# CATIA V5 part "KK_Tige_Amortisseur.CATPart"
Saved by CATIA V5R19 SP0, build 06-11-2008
Part number: Tige d'amortisseur
Bounding box of the stored display mesh (mm): x -480 to 480, y 640 to 1407.954, z -3231.87 to -864
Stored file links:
  G:\Khaled_CFAO_2011\ST2M\ST2M_GR2\aboulegue\Khaled\CAD_thinkMOTION\KK_Tige_Amortisseur.CATPart
  G:\Khaled_CFAO_2011\ST2M\ST2M_GR2\aboulegue\Khaled\CAD_thinkMOTION\KK_Train_Atterrissage.CATProduct
  G:\Khaled_CFAO_2011\ST2M\ST2M_GR2\aboulegue\Khaled\CAD_thinkMOTION\KK_Squelette_TigeAmortisseur.CATPart
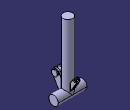
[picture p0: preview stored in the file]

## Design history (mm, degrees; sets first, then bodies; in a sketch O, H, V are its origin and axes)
Set1
  Plane1 "Plan de reference tige amortisseur": linked copy from another document
  Line1: linked copy from another document
  Point1: linked copy from another document
  Point2 "Point.17": linked copy from another document
  Plane2 "Plan de reference tige amortisseur2": linked copy from another document
  Line2: linked copy from another document
  Line3: linked copy from another document
  Point3: linked copy from another document
  Line4: linked copy from another document
  Point4: linked copy from another document
Body1 (main body)
  Sketch1 on Plane1, origin (0, 1056, 0), H (-1, 0, 0), V (0, 0, 1)
    point P1 (0, -864)
    line L1 (0, -864) -> (160, -864)
    line L2 (160, -864) -> (160, -3072)
    line L3 (160, -3072) -> (0, -3072)
    line L4 (0, -3072) -> (0, -864)
    point P4 (0, -3072)
    reference projected line E1 (0, -864) -> (0, -3072) from Line1
    reference projected point E2 (0, -3072) from Point1
    reference projected point E3 (0, -864) from Point2
    length L3 = 160
    horizontal: L1 H, L3 H
    vertical: L2 V, L4 V
    coincidence: E1 L4, E2 P4, P1 E3
  Shaft1: profile Sketch1, axis Line1, angle 360
  Sketch2 on Plane2, origin (0, 0, 0), H (0, 1, 0), V (0, 0, 1)
    circle A1 centre (1056, -3072) radius 160
    point P1 (1056, -3072)
    reference projected point E1 (1056, -3072) from Point1
    radius A1 = 160
    coincidence: E1 P1
  Pad1: profile Sketch2, direction (1, 0, 0), length 480, mirrored extent
  Plane3: type Normal, Curve Line3, RefPoint Point1
  Sketch3 on Plane3, origin (0, -982.6138, -1848.8317), H (1, 0, 0), V (0, -0.8575, 0.5145)
    line L1 (32, -2313.4118) -> (64, -2313.4118)
    line L2 (64, -2313.4118) -> (64, -2441.4118)
    line L3 (64, -2441.4118) -> (32, -2441.4118)
    line L4 (32, -2441.4118) -> (32, -2313.4118)
    point P5 (-64, -2313.4118)
    line L5 (-64, -2313.4118) -> (-32, -2313.4118)
    line L6 (-32, -2313.4118) -> (-32, -2441.4118)
    line L7 (-32, -2441.4118) -> (-64, -2441.4118)
    line L8 (-64, -2441.4118) -> (-64, -2313.4118)
    point P7 (-32, -2441.4118)
    reference projected line E1 (0, -1338.3529) -> (0, -2377.4118) from Line1
    reference projected line E2 (0, -1338.3529) -> (0, -2377.4118) from Line1
    reference projected line E3 (-200, -2377.4118) -> (200, -2377.4118) from Line2
    reference projected line E4 (-200, -2377.4118) -> (200, -2377.4118) from Line2
    length L3 = 32
    length L7 = 32
    distance E1 L4 = 32
    distance L6 E2 = 32
    distance E3 L7 = 64
    distance E4 L5 = 64
    horizontal: L1 H, L3 H, L5 H, L7 H
    vertical: L2 V, L4 V, L6 V, L8 V
    coincidence: P5 L1, P7 L3
  Pad2: profile Sketch3, direction (0, 0.5145, 0.8575), length 700
  Sketch4 on face of Pad2 from Sketch3.L2, origin (64, 0, 0), H (0, 1, 0), V (0, 0, 1)
    arc A1 centre (1344, -2592) radius 64 from (1398.8795, -2624.9277) to (1289.1205, -2559.0723) ccw
    point P1 (1344, -2592)
    reference projected point E1 (1344, -2592) from Point3
    reference projected line E2 (1114.2035, -3099.3879) -> (1474.3505, -2499.1428) from edge [face of Pad2 from Sketch3.L3 | face of Pad2 from Sketch3.L2]
    line L1 (1381.7297, -2404.7235) -> (1289.1205, -2559.0723)
    line L2 (1398.8795, -2624.9277) -> (1491.4888, -2470.579)
    line L3 (1491.4888, -2470.579) -> (1381.7297, -2404.7235)
    reference projected line E3 (997.7965, -3044.6121) -> (1357.9436, -2444.3671) from edge [face of Pad2 from Sketch3.L2 | face of Pad2 from Sketch3.L1]
    reference projected line E4 (1114.2035, -3099.3879) -> (1474.3505, -2499.1428) from edge [face of Pad2 from Sketch3.L3 | face of Pad2 from Sketch3.L2]
    length L2 = 180
    length L1 = 180
    coincidence: P1 E1, L1 E3, L2 E4
    tangency: A1 E2
  Pocket1: profile Sketch4, direction (-1, 0, 0), length 64
  Sketch5 on face of Pad2 from Sketch3.L8, origin (-64, 0, 0), H (0, -1, 0), V (0, 0, 1)
    arc A1 centre (-1344, -2592) radius 64 from (-1289.1205, -2559.0723) to (-1398.8795, -2624.9277) ccw
    point P1 (-1344, -2592)
    reference projected point E1 (-1344, -2592) from Point3
    reference projected line E2 (-1114.2035, -3099.3879) -> (-1474.3505, -2499.1428) from edge [face of Pad2 from Sketch3.L8 | face of Pad2 from Sketch3.L7]
    line L1 (-1491.4888, -2470.579) -> (-1398.8795, -2624.9277)
    line L2 (-1289.1205, -2559.0723) -> (-1495.7947, -2214.6152)
    line L3 (-1495.7947, -2214.6152) -> (-1491.4888, -2470.579)
    reference projected line E3 (-1114.2035, -3099.3879) -> (-1474.3505, -2499.1428) from edge [face of Pad2 from Sketch3.L8 | face of Pad2 from Sketch3.L7]
    reference projected line E4 (-997.7965, -3044.6121) -> (-1357.9436, -2444.3671) from edge [face of Pad2 from Sketch3.L5 | face of Pad2 from Sketch3.L8]
    length L1 = 180
    length L3 = 256
    coincidence: E1 P1, E3 L1, L2 E4
    tangency: A1 E2
    parallelism: L2 L1
  Pocket2: profile Sketch5, direction (1, 0, 0), length 64
  Fillet1: radius 5, on face of Pad2 from Sketch3.L8; face of Pad2 from Sketch3.L2; edge [face of Pad2 from Sketch3.L4 | face of Pad2 from Sketch3.L3]; edge [face of Pocket1 from Sketch4.A1 | face of Pad2 from Sketch3.L4]; edge [face of Pad2 from Sketch3.L4 | face of Shaft1 from Sketch1.L2]; edge [face of Pocket2 from Sketch5.A1 | face of Pad2 from Sketch3.L6]; edge [face of Pad2 from Sketch3.L7 | face of Pad2 from Sketch3.L6]; edge [face of Pad2 from Sketch3.L6 | face of Shaft1 from Sketch1.L2]
  Sketch6 on face of Pad2 from Sketch3.L2, origin (64, 0, 0), H (0, 1, 0), V (0, 0, 1)
    circle A1 centre (1344, -2592) radius 32
    point P1 (1344, -2592)
    reference projected point E1 (1344, -2592) from Point3
    radius A1 = 32
    coincidence: P1 E1
  Pocket3: profile Sketch6, direction (-1, 0, 0), through (limit type 3)
  Plane4: type Normal, Curve Line4, RefPoint Point1
  Sketch7 on Plane4, origin (0, 1634.8235, -2724.7059), H (-1, 0, 0), V (0, 0.8575, 0.5145)
    line L1 (128, -547.0184) -> (64, -547.0184)
    line L2 (64, -547.0184) -> (64, -803.0184)
    line L3 (64, -803.0184) -> (128, -803.0184)
    line L4 (128, -803.0184) -> (128, -547.0184)
    point P5 (-64, -547.0184)
    line L5 (-64, -547.0184) -> (-128, -547.0184)
    line L6 (-128, -547.0184) -> (-128, -803.0184)
    line L7 (-128, -803.0184) -> (-64, -803.0184)
    line L8 (-64, -803.0184) -> (-64, -547.0184)
    point P7 (-128, -803.0184)
    reference projected line E1 (0, -181.1025) -> (0, -675.0184) from Line3
    reference projected line E2 (0, -181.1025) -> (0, -675.0184) from Line3
    reference projected line E3 (200, -675.0184) -> (-200, -675.0184) from Line2
    distance E1 L8 = 64
    length L7 = 64
    length L3 = 64
    distance L2 E2 = 64
    length L6 = 256
    distance L5 E3 = 128
    horizontal: L1 H, L3 H, L5 H, L7 H
    vertical: L2 V, L4 V, L6 V, L8 V
    coincidence: P5 L1, P7 L3
  Pad3: profile Sketch7, direction (0, -0.5145, 0.8575), length 700
  Sketch8 on face of Pad3 from Sketch7.L6, origin (128, 0, 0), H (0, 1, 0), V (0, 0, 1)
    arc A1 centre (768, -2592) radius 128 from (877.7591, -2526.1445) to (658.2409, -2657.8555) ccw
    point P1 (768, -2592)
    reference projected point E1 (768, -2592) from Point4
    line L1 (658.2409, -2657.8555) -> (565.6317, -2503.5067)
    line L2 (785.1499, -2371.7958) -> (877.7591, -2526.1445)
    reference projected line E2 (946.2409, -3137.8555) -> (586.0939, -2537.6104) from edge [face of Pad3 from Sketch7.L6 | face of Pad3 from Sketch7.L7]
    reference projected line E3 (1165.7591, -3006.1445) -> (805.6121, -2405.8995) from edge [face of Pad3 from Sketch7.L5 | face of Pad3 from Sketch7.L6]
    line L3 (565.6317, -2503.5067) -> (785.1499, -2371.7958)
    length L1 = 180
    length L2 = 180
    coincidence: P1 E1, L1 E2, L2 E3
    tangency: L1 A1, L2 A1
  Pocket4: profile Sketch8, direction (-1, 0, 0), length 64
  Sketch9 on face of Pad3 from Sketch7.L4, origin (-128, 0, 0), H (0, -1, 0), V (0, 0, 1)
    arc A1 centre (-768, -2592) radius 128 from (-658.2409, -2657.8555) to (-877.7591, -2526.1445) ccw
    point P1 (-768, -2592)
    reference projected point E1 (-768, -2592) from Point4
    line L1 (-877.7591, -2526.1445) -> (-785.1499, -2371.7958)
    line L2 (-785.1499, -2371.7958) -> (-565.6317, -2503.5067)
    line L3 (-565.6317, -2503.5067) -> (-658.2409, -2657.8555)
    reference projected line E2 (-946.2409, -3137.8555) -> (-586.0939, -2537.6104) from edge [face of Pad3 from Sketch7.L3 | face of Pad3 from Sketch7.L4]
    reference projected line E3 (-1165.7591, -3006.1445) -> (-805.6121, -2405.8995) from edge [face of Pad3 from Sketch7.L4 | face of Pad3 from Sketch7.L1]
    length L3 = 180
    coincidence: P1 E1, L3 E2, L1 E3
    perpendicularity: L2 L1
    tangency: L3 A1
  Pocket5: profile Sketch9, direction (1, 0, 0), length 64
  Sketch10 on face of Pad3 from Sketch7.L6, origin (128, 0, 0), H (0, 1, 0), V (0, 0, 1)
    circle A1 centre (768, -2592) radius 80
    point P1 (768, -2592)
    reference projected point E1 (768, -2592) from Point4
    radius A1 = 80
    coincidence: P1 E1
  Pocket6: profile Sketch10, direction (-1, 0, 0), through (limit type 3)
  Fillet2: radius 5, on edge [face of Pad3 from Sketch7.L2 | face of Shaft1 from Sketch1.L2]; edge [face of Pad3 from Sketch7.L2 | face of Pad3 from Sketch7.L3]; edge [face of Pocket5 from Sketch9.A1 | face of Pad3 from Sketch7.L2]; edge [face of Pad3 from Sketch7.L1 | face of Pad3 from Sketch7.L2]; edge [face of Pad3 from Sketch7.L4 | face of Pad3 from Sketch7.L1]; edge [face of Pad3 from Sketch7.L4 | face of Pocket5 from Sketch9.A1]; edge [face of Pad3 from Sketch7.L3 | face of Pad3 from Sketch7.L4]; edge [face of Pad3 from Sketch7.L4 | face of Pad1 from Sketch2.A1]; edge [face of Shaft1 from Sketch1.L2 | face of Pad3 from Sketch7.L4]; edge [face of Pad3 from Sketch7.L8 | face of Shaft1 from Sketch1.L2]; edge [face of Pad3 from Sketch7.L7 | face of Pad3 from Sketch7.L8]; edge [face of Pocket4 from Sketch8.A1 | face of Pad3 from Sketch7.L8]; edge [face of Pad3 from Sketch7.L8 | face of Pad3 from Sketch7.L5]; edge [face of Pad3 from Sketch7.L6 | face of Pad3 from Sketch7.L7]; edge [face of Pad3 from Sketch7.L6 | face of Pocket4 from Sketch8.A1]; edge [face of Pad3 from Sketch7.L5 | face of Pad3 from Sketch7.L6]; edge [face of Shaft1 from Sketch1.L2 | face of Pad3 from Sketch7.L6]; edge [face of Pad3 from Sketch7.L6 | face of Pad1 from Sketch2.A1]
  Sketch11 on face of Pad3 from Sketch7.L6, origin (128, 0, 0), H (0, 1, 0), V (0, 0, 1)
    circle A1 centre (768, -2592) radius 96
    point P1 (768, -2592)
    reference projected point E1 (768, -2592) from Point4
    radius A1 = 96
    coincidence: P1 E1
  Pad4: profile Sketch11, direction (1, 0, 0), length 32
  Sketch12 on start face of Pad4, origin (128, 0, 0), H (0, -1, 0), V (0, 0, 1)
    circle A1 centre (-768, -2592) radius 80
    reference projected circle E1 centre (-768, -2592) radius 80 from edge [start face of Pad4 | face of Pocket6 from Sketch10.A1]
    coincidence: E1 A1
  Pad5: profile Sketch12, direction (-1, 0, 0), length 266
